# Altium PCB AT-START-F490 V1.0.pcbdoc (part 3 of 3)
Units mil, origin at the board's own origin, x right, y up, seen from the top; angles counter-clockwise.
Board outline 15424.54 x 3536.36 mil, 2 copper layers (Top Layer, Bottom Layer); 130 components, 126 nets, 528 pads, 715 vias.
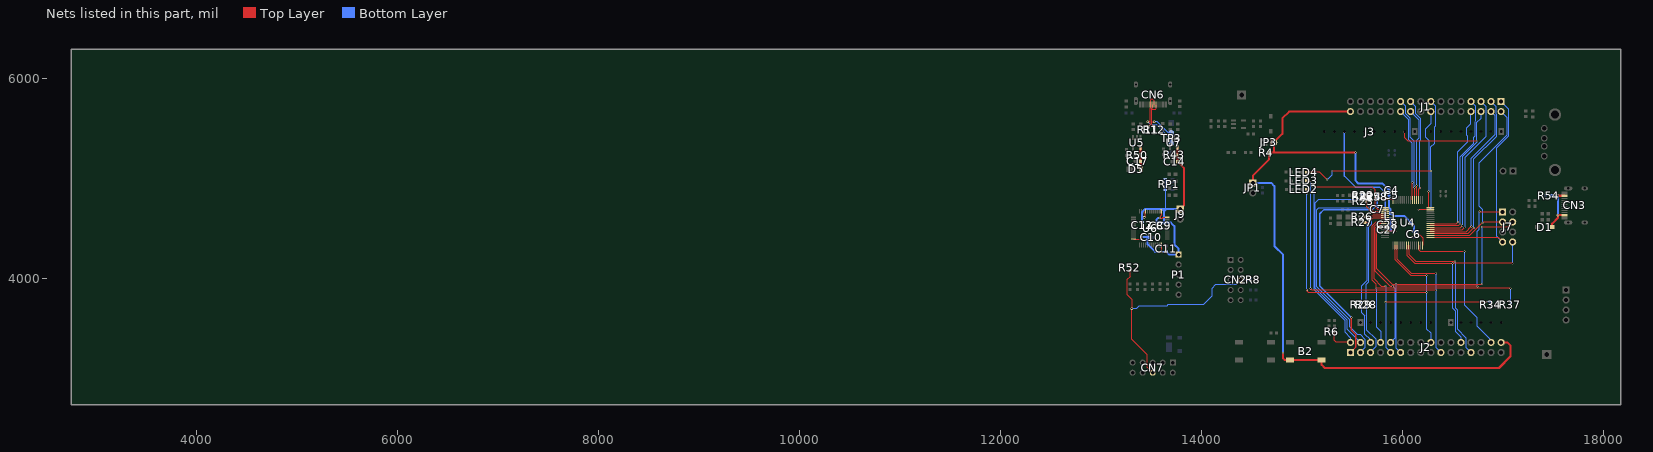
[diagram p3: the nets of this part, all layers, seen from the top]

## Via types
v1: diameter 19.68, hole 11.81, Top Layer to Bottom Layer, 622 vias
v2: diameter 19.69, hole 11.81, Top Layer to Bottom Layer, 42 vias
v3: diameter 23.62, hole 11.81, Top Layer to Bottom Layer, 17 vias
v4: diameter 27.56, hole 13.78, Top Layer to Bottom Layer, 15 vias
v5: diameter 19.7, hole 11.81, Top Layer to Bottom Layer, 10 vias
v6: diameter 24, hole 12, Top Layer to Bottom Layer, 7 vias
v7: diameter 27.56, hole 15.75, Top Layer to Bottom Layer, 2 vias

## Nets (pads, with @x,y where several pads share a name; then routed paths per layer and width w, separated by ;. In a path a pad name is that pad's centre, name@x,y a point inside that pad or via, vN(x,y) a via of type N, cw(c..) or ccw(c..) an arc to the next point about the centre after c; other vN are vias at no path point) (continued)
PB11: J2.30 U4.30 | length 1523.4
  Top Layer w6: U4.30@16161.84,4334.34 16161.84,4289.61 16176.7,4274.76 16617.38,4274.76 v1(16617.58,4274.56)
  Bottom Layer w6: v1(16617.58,4274.56) 16617.58,3743.57 16740.58,3620.57 16740.58,3533.57 J2.30@16883.87,3390.28 ; J2.30@16883.88,3368.14 J2.30@16883.88,3390.26
PB12: J1.1 J7.7 U4.33 | length 2241.6
  Top Layer w6: U4.33@16279.94,4413.07 16952.97,4413.07 J7.7@16998.88,4367.16
  Bottom Layer w6: J1.1@16983.44,5765.86 17056.58,5692.73 17056.58,5420.56 16937.58,5301.56 16937.58,4428.47 J7.7@16998.88,4367.16
PB13: J1.2 J7.3 U4.34 | length 2038.6
  Top Layer w6: U4.34@16279.94,4432.76 16673.28,4432.76 16807.69,4567.16 J7.3@16998.88,4567.16
  Bottom Layer w6: v1(16796.58,4555.56) 16796.58,4692.56 16760.58,4728.56 16760.58,5153.56 17039.58,5432.56 17039.58,5609.73 J1.2@16983.44,5665.86
PB14: J1.3 U4.35 | length 1831.9
  Top Layer w6: U4.35@16279.94,4452.44 16657.45,4452.44 v1(16713.58,4508.56)
  Bottom Layer w6: v1(16713.58,4508.56) 16713.58,5194.56 16940.58,5421.56 16940.58,5634.56 16933.58,5641.56 16933.58,5715.73 J1.3@16883.44,5765.86
PB15: J1.4 U4.36 | length 1689.3
  Top Layer w6: U4.36@16279.94,4472.13 16638.14,4472.13 v1(16688.58,4522.56)
  Bottom Layer w6: v1(16688.58,4522.56) 16688.58,5200.56 16926.58,5438.56 16926.58,5622.73 J1.4@16883.44,5665.86
PC0: J2.8 R37.1 U4.8 | length 2824.2
  Top Layer w6: U4.8@15827.2,4570.55 15826.45,4571.3 15738.83,4571.3 15698.56,4531.03 15698.56,3988.28 15740.1,3946.74 15740.1,3907.72 v1(15739.58,3907.2) 17075.94,3907.2 v1(17076.58,3906.57)
  Bottom Layer w6: v1(15739.58,3907.2) 15739.58,3522.95 15783.88,3478.65 J2.8@15783.88,3368.14 ; R37.1@17076.58,3763.97 v1(17076.58,3906.57)
PC1: J2.9 R34.1 U4.9 | length 2523.7
  Top Layer w6: U4.9@15827.2,4550.87 15743.56,4550.87 15713.42,4520.73 15713.42,4007.78 15792.64,3928.57 v1(15834.58,3928.57) ; v1(15834.61,3768.57) v2(16842.58,3768.57)
  Bottom Layer w6: v1(15834.58,3928.57) v1(15834.61,3768.57) 15834.58,3317.45 J2.9@15883.88,3268.14 ; v2(16842.58,3768.57) R34.1@16880.08,3768.57 ; R34.1@16878.83,3769.82 R34.1@16880.08,3768.57 ; R34.1@16881.83,3766.82 R34.1@16880.08,3768.57
PC2: J2.10 J7.1 U4.10 | length 3185.5
  Top Layer w6: U4.10@15827.2,4531.18 15756.07,4531.18 15727.8,4502.91 15727.8,4080.72 15880.95,3927.57 v1(15903.58,3927.57) 16745.58,3927.57 v1(16746.58,3926.57) ; v1(16766.58,4669.56) 16996.47,4669.56 J7.1@16998.88,4667.16
  Bottom Layer w6: J2.10@15883.88,3368.14 15924.58,3408.84 15924.58,3906.57 v1(15903.58,3927.57) ; v1(16746.58,3926.57) 16746.58,4474.05 16766.58,4494.05 v1(16766.58,4669.56)
PC3: J2.11 J7.4 U4.11 | length 3185.9
  Top Layer w6: U4.11@15827.2,4511.5 15775.09,4511.5 15742.77,4479.18 15742.77,4104.83 15899.81,3947.79 v1(15936.58,3947.79) ; v1@15934.58,3949.79 v1(15936.58,3947.79) ; v1(16795.28,4517.56) 17049.28,4517.56 J7.4@17098.88,4567.16 ; v1(16795.58,3948.57) 16794.58,3947.57 15936.8,3947.57 v1(15936.58,3947.79)
  Bottom Layer w6: v1(15936.58,3947.79) 15936.58,3315.45 J2.11@15983.88,3268.14 ; v1(16795.28,4517.56) 16795.28,3948.86 v1(16795.58,3948.57)
PC4: J2.24 J7.8 U4.24 | length 2222.8
  Top Layer w6: U4.24@16043.73,4334.34 16044.01,4334.07 16044.01,4235.23 16124.67,4154.56 v2(16498.58,4154.56) v1(17099.58,4154.56)
  Bottom Layer w6: v2(16498.58,4154.56) 16498.58,3713.57 16526.58,3685.57 16526.58,3480.03 16583.88,3422.74 J2.24@16583.88,3368.14 ; J7.8@17098.88,4367.16 17099.58,4366.47 v1(17099.58,4154.56)
PC5: J2.25 U4.25 | length 1552.9
  Top Layer w6: U4.25@16063.41,4334.34 16063.41,4243.68 16133.53,4173.56 v2(16525.58,4173.56)
  Bottom Layer w6: v2(16525.58,4173.56) 16525.58,3714.43 16544.58,3695.43 16544.58,3503.7 16632.58,3415.7 16632.58,3319.43 J2.25@16683.88,3268.14
PC6: J1.5 U4.37 | length 1705.6
  Top Layer w6: U4.37@16279.94,4491.81 16596.82,4491.81 v1(16619.58,4514.56)
  Bottom Layer w6: v1(16619.58,4514.56) 16619.58,5207.56 16828.58,5416.56 16828.58,5720.73 J1.5@16783.44,5765.86
PC7: J1.6 J3.2 U4.38 | length 2329.7
  Top Layer w6: J3.2@16023.88,5466.56 16023.88,5407.49 16060.81,5370.56 v2(16742.58,5370.56) ; U4.38@16279.94,4511.5 16576.51,4511.5 v1(16596.42,4531.41)
  Bottom Layer w6: v1(16596.42,4531.41) 16596.42,5215.93 16742.58,5362.08 v2(16742.58,5370.56) 16742.58,5559.56 16783.44,5600.44 J1.6@16783.44,5665.86
PC8: J1.7 U4.39 | length 1606.8
  Top Layer w6: U4.39@16279.94,4531.18 16557.19,4531.18 v1(16575.22,4549.21)
  Bottom Layer w6: v1(16575.22,4549.21) 16575.22,5218.21 16708.87,5351.85 16708.87,5408.23 16726.58,5425.94 16726.58,5566.56 16733.58,5573.56 16733.58,5717.56 16685.28,5765.86 J1.7@16683.44,5765.86
PC9: J1.8 U4.40 | length 1442.8
  Top Layer w6: U4.40@16279.94,4551.69 16538.7,4551.69 v2(16553.58,4566.56)
  Bottom Layer w6: v2(16553.58,4566.56) 16553.58,5265.56 16652.58,5364.56 16652.58,5418.56 16640.58,5430.56 16640.58,5503.56 16683.44,5546.44 J1.8@16683.44,5665.86
PC10: J1.19 U4.51 | length 1030.1
  Top Layer w6: U4.51@16161.84,4787.08 16161.84,4893.64 v2(16174.77,4906.56)
  Bottom Layer w6: J1.19@16083.44,5765.86 16134.58,5714.73 16134.58,5642.56 16184.58,5592.56 16184.58,5386.56 16174.77,5376.76 v2(16174.77,4906.56)
PC11: J1.20 U4.52 | length 925
  Top Layer w6: U4.52@16142.15,4787.08 16142.15,4930.14 v2(16142.58,4930.56)
  Bottom Layer w6: J1.20@16083.44,5665.86 16168.58,5580.73 16168.58,5404.56 16142.58,5378.56 v2(16142.58,4930.56)
PC12: J1.21 U4.53 | length 1036.4
  Top Layer w6: v2(16120.57,4910.16) 16122.47,4908.25 U4.53@16122.47,4787.08
  Bottom Layer w6: J1.21@15983.44,5765.86 16032.58,5716.73 16032.58,5644.56 16078.58,5598.56 16078.58,5412.56 16120.57,5370.57 v2(16120.57,4910.16)
PC13: J2.2 R6.2 U4.2 | length 2859.6
  Top Layer w6: v1(15116.58,4912.56) 15702.58,4912.56 15728.58,4886.56 15728.58,4719.56 15759.48,4688.66 U4.2@15827.2,4688.66 ; R6.2@15317.85,3474.57 15322.76,3474.57 15320.58,3472.38 15320.58,3391.57 15344,3368.14 J2.2@15483.88,3368.14
  Bottom Layer w6: v1(15116.58,4912.56) 15116.58,3896.57 15425.58,3587.57 15425.58,3472.57 15483.88,3414.27 J2.2@15483.88,3368.14
PC14: J2.3 R24.2 | length 2278.3
  Bottom Layer w6: J2.3@15583.88,3268.14 15633.58,3317.84 15633.58,3396.57 15586.58,3443.57 15554.58,3443.57 15475.58,3522.57 15475.58,3593.57 15147.58,3921.57 15147.58,4688.56 15169.58,4710.56 15659.58,4710.56 15689.58,4740.56 R24.2@15689.58,4794.28
PC14/LEXT_IN: R22.1 R24.1 U4.3 | length 429.8
  Top Layer w6: R22.1@15637.08,4832.56 15688.55,4832.56 ; v1(15688.58,4881.56) 15688.58,4832.56 15688.58,4696.56 15716.16,4668.98 U4.3@15827.2,4668.98
  Bottom Layer w6: v1(15688.58,4881.56) 15689.58,4880.56 R24.1@15689.58,4838.69
PC15: J2.4 R25.2 | length 2051.5
  Bottom Layer w6: J2.4@15583.58,3368.57 15450.58,3501.57 15450.58,3590.57 15132.58,3908.57 15132.58,4756.68 15170.18,4794.28 15593.58,4794.28
PC15/LEXT_OUT: R23.1 R25.1 U4.4 | length 399.8
  Top Layer w6: R23.1@15639.08,4774.56 v1(15639.08,4739.92) 15639.08,4722.06 15711.85,4649.29 U4.4@15827.2,4649.29
  Bottom Layer w6: R25.1@15605.58,4838.69 15605.69,4838.56 15633.58,4838.56 15639.08,4833.06 v1(15639.08,4739.92)
PD2: J1.22 U4.54 | length 927.5
  Top Layer w6: v2@16100.16,4959.76 16100.16,4790.7 16102.78,4788.08 U4.54@16102.78,4787.08
  Bottom Layer w6: J1.22@15983.58,5665.56 16064.58,5584.56 16064.58,5387.45 16099.16,5352.87 v2(16099.16,4959.76)
PF0: J2.5 R28.2 | length 511.8
  Bottom Layer w6: R28.2@15643.58,3721.28 15642.58,3720.28 15642.58,3495.57 15733.58,3404.57 15733.58,3323.57 15683.88,3273.86 J2.5@15683.88,3268.14
PF0/HEXT_IN: R26.1 R28.1 U4.5 | length 1085.9
  Top Layer w6: R26.1@15628.08,4616.56 15629.17,4615.47 v1(15671.97,4615.33) 15686.43,4629.78 15778.95,4629.78 15779.08,4629.91 15826.9,4629.91 U4.5@15827.2,4629.61
  Bottom Layer w6: R28.1@15643.58,3765.68 15643.58,3948.57 15665.58,3970.57 15665.58,4518.7 15694.58,4547.7 15694.58,4592.72 v1(15671.97,4615.33)
PF1: J2.6 R29.2 | length 393.2
  Bottom Layer w6: R29.2@15589.58,3722.28 15589.58,3670.57 15628.58,3631.57 15628.58,3447.57 15683.88,3392.26 J2.6@15683.88,3368.14
PF1/HEXT_OUT: R27.1 R29.1 U4.6 | length 1051.4
  Top Layer w6: R27.1@15628.08,4562.56 v1(15670.58,4562.56) 15670.58,4568.08 15711.91,4609.41 15826.7,4609.41 U4.6@15827.2,4609.92
  Bottom Layer w6: R29.1@15589.58,3766.68 15589.58,3925.57 15647.58,3983.57 15647.58,4539.56 v1(15670.58,4562.56)
PF4: J2.18 LED2.2 U4.18 | length 3412.9
  Top Layer w6: v1(15049.23,3891.48) 15049.23,3881.04 15064.35,3865.91 v1(16240.58,3865.91) ; v1(15049.23,4849.22) 15049.53,4849.52 LED2.2@15049.53,4890.77 ; U4.18@15925.62,4334.34 15925.62,4195.52 16085.58,4035.57 v2(16240.58,4035.57)
  Bottom Layer w6: v1(15049.23,3891.48) v1(15049.23,4849.22) ; v2(16240.58,4035.57) v1(16240.58,3865.91) 16240.58,3506.57 16283.88,3463.28 J2.18@16283.88,3368.14
PF5: J2.19 LED3.2 U4.19 | length 3753.8
  Top Layer w6: LED3.2@15049.53,4976.77 v1(15085.37,4976.77) ; v1(15085.37,3904.35) 15102.48,3887.25 v1(16333.58,3887.25) ; U4.19@15945.3,4334.34 15945.3,4200.84 16090.58,4055.57 v2(16333.58,4055.57)
  Bottom Layer w6: v1(15085.37,3904.35) v1(15085.37,4976.77) ; v2(16333.58,4055.57) v1(16333.58,3887.25) 16333.58,3318.43 J2.19@16383.88,3268.14
PF6: J1.15 LED4.2 U4.47 | length 2675.8
  Top Layer w6: LED4.2@15049.53,5060.77 15179.37,5060.77 v1(15251.58,4988.56) ; v1(15302.58,5074.56) v2(16284.58,5074.56) ; v1@16158.95,4688.66 U4.47@16279.94,4688.66
  Bottom Layer w6: v1(15251.58,4988.56) 15302.58,5039.56 v1(15302.58,5074.56) ; v1(16158.9,4688.61) 16268.53,4688.61 16284.58,4704.66 v2(16284.58,5074.56) 16284.58,5314.56 16322.58,5352.56 16322.58,5512.56 16332.58,5522.56 16332.58,5716.73 J1.15@16283.44,5765.86
PF7: J1.16 U4.48 | length 1008.5
  Top Layer w6: v2(16261.58,4870.56) 16263.12,4869.02 16263.12,4711.82 16266.6,4708.35 U4.48@16279.94,4708.35
  Bottom Layer w6: v2(16261.58,4870.56) 16262.58,4871.56 16262.58,5382.56 16230.58,5414.56 16230.58,5490.56 16283.44,5543.44 J1.16@16283.44,5665.86
SWO: CN2.6 CN7.6 R8.2 R52.1 | length 2484.5
  Top Layer w6: R52.1@13290.15,4081.97 13290.15,4024.01 13256.58,3990.45 13256.58,3846.57 13306.58,3796.57 v3(13306.58,3704.57) 13306.58,3399.57 13462.58,3243.57 13462.58,3119.78 CN7.6@13515.34,3067.01
  Bottom Layer w6: v3(13306.58,3704.57) 13350.58,3704.57 13374.58,3728.57 13653.58,3728.57 13665.58,3740.57 14016.58,3740.57 14101.58,3825.57 14101.58,3904.57 14139.58,3942.57 14343.65,3942.57 CN2.6@14390.92,3989.84 ; CN2.6@14390.97,3989.89 R8.2@14490.58,3989.89
USB+: CN6.A6 CN6.B6 R11.1 TP3.3 | length 723.2
  Top Layer w11.2: v4(13466.68,5563.67) 13490.33,5563.67 ; R11.1@13469.58,5515.56 13490.33,5536.31 13490.33,5563.67 ; CN6.A6@13528.38,5735.27 13528.38,5774.77 13516.58,5786.56 13499.58,5786.56 13489.58,5776.56 13489.58,5735.77 CN6.B6@13489.08,5735.27 13489.08,5699.11 13490.33,5697.86 13490.33,5563.67
  Bottom Layer w11.2: v4(13466.68,5563.67) 13497.78,5532.56 13553.58,5532.56 13699.92,5386.22 TP3.3@13699.92,5351.02
USB-: CN6.A7 CN6.B7 R12.1 TP3.2 | length 554.9
  Top Layer w11.2: CN6.A7@13508.77,5735.27 13508.77,5699.11 13507.52,5697.86 13507.52,5683.94 ; R12.1@13528.58,5515.23 13507.52,5536.27 13507.52,5563.67 ; v4(13531.68,5563.67) 13507.52,5563.67 ; CN6.B7@13548.08,5735.27 13548.08,5693.06 13539.58,5684.56 13508.15,5684.56 13507.52,5683.94 ; 13507.52,5563.67 13507.52,5683.94
  Bottom Layer w11.2: v4(13531.68,5563.67) 13561.47,5563.67 13674.12,5451.02 TP3.2@13699.92,5451.02
VBUS_FS: CN3.A4B9 CN3.B4A9 D1.1 R54.2 | length 531.4
  Top Layer w20: D1.1@17492.58,4515.56 17492.58,4550.28 17549.08,4606.78 v6(17549.08,4635.06) CN3.A4B9@17615.28,4635.06 ; v6(17549.08,4827.06) 17550.08,4828.06 CN3.B4A9@17615.28,4828.06
  Bottom Layer w6: R54.2@17485.58,4827.56 v6@17548.58,4827.56
  Bottom Layer w20: v6@17548.58,4827.56 v6(17549.08,4827.06) v6(17549.08,4635.06)
VCC: C8.1 C9.1 C10.1 C11.1 C12.1 C14.1 J9.1 P1.1 R43.2 RP1.1 RP1.2 RP1.3 RP1.4 U6.1 U6.9 U6.24 U6.36 U6.48 U7.5 | length 3073.1
  Top Layer w10: U6.24@13324.5,4397.43 13390.33,4397.43 v3(13407.92,4415.02) ; v3(13430.58,4612.56) 13442.6,4624.6 U6.9@13442.6,4673.02 ; U6.36@13600.08,4338.36 13600.08,4270.27 v3(13600.34,4270.02) ; U6.1@13600.08,4673.02 13600.08,4632.76 13583.34,4616.02 v3(13583.34,4606.02) 13612.34,4606.02 13620.3,4613.97 U6.48@13659.15,4613.97
  Top Layer w20: C14.1@13764.14,5165.56 13827.58,5102.12 13827.58,4732.16 J9.1@13789.38,4693.97 ; C14.1@13764.34,5166.3 U7.5@13764.34,5307.9
  Bottom Layer w10: 13638.82,4683.98 13640.58,4685.73 13640.58,4694.02 RP1.1@13640.58,4887.56 RP1.2@13640.58,4922.99 RP1.3@13640.58,4958.44 RP1.4@13640.58,4993.86
  Bottom Layer w20: C12.1@13407.34,4560.02 13407.34,4664.02 13437.34,4694.02 13610.53,4694.02 ; 13407.35,4614.02 13429.12,4614.02 v3(13430.58,4612.56) ; v3(13407.92,4415.02) 13465.34,4415.02 13465.34,4345.02 13540.34,4270.02 v3(13600.34,4270.02) 13650.58,4273.06 13681.08,4242.56 P1.1@13772.58,4242.56 13772.58,4300.56 13730.34,4342.8 13730.34,4526.02 13696.34,4560.02 C9.1@13628.34,4560.02 ; v3(13583.34,4606.02) 13567.34,4606.02 13554.34,4593.02 13554.34,4560.02 C9.1@13628.34,4560.02 ; J9.1@13789.34,4694.02 13649.06,4694.02 ; 13610.53,4694.02 13610.53,4691.52 13628.34,4673.7 ; 13610.53,4694.02 13640.58,4694.02 13649.06,4694.02 ; C9.1@13628.34,4560.02 13628.34,4673.7 ; 13628.34,4673.7 13638.82,4683.98 13649.06,4694.02
VCC3.5V: C17.1 D5.2 R50.2 U5.5 | length 488.1
  Top Layer w20: U5.5@13395.58,5305.56 13395.15,5110.74 D5.2@13396.33,5109.56
  Top Layer w25: D5.2@13389.33,5099.56 D5.2@13395.14,5105.38 ; U5.5@13395.15,5305.9 C17.1@13395.14,5173.56 ; D5.2@13397.33,5091.56 13395.14,5093.76 D5.2@13395.14,5105.38 ; D5.2@13395.15,5105.39 13395.15,5110.74 C17.1@13395.14,5173.56 ; D5.2@13395.14,5105.38 C17.1@13395.14,5173.56
VDD: B2.1 B2.2 C4.1 C5.1 C6.1 C7.1 J1.32 J2.1 J2.32 JP1.1 JP3.2 L1.1 R4.1 R58.1 R58.2 U4.1 U4.32 U4.64 | length 10829.2
  Top Layer w8: v1(15795.42,4732.19) 15795.42,4724.91 15796.98,4723.34 15796.98,4716.21 U4.1@15800,4713.19 ; U4.1@15800.26,4713.45 U4.1@15800,4713.19 ; U4.1@15827.2,4708.35 15800,4708.35 U4.1@15800,4713.19 ; v1(15869.11,4792.31) 15900.71,4792.31 U4.64@15905.93,4787.08 ; v1(16156.5,4454.44) 16201.21,4409.72 U4.32@16201.21,4334.34
  Top Layer w15: J2.1@15483.88,3268.14 15534.58,3318.84 15534.58,3446.57 15493.58,3487.57 v1(15493.58,3614.57) ; v1(15799.83,4792.31) v1(15869.11,4792.31)
  Top Layer w20: JP1.1@14511.57,4956.56 14511.57,5028.56 14675.08,5192.06 R4.1@14675.08,5258.56 14720.43,5258.56 14720.58,5258.71 ; v1(14813.58,3262.57) 14813.58,3209.57 14830.58,3192.57 14880.68,3192.57 B2.2@14881.09,3192.99 B2.1@15196.06,3192.99 15196.06,3144.09 15226.58,3113.57 16962.58,3113.57 17076.58,3227.57 17076.58,3338.57 17046.58,3368.57 16984.31,3368.57 J2.32@16983.88,3368.14 ; J1.32@15483.44,5665.86 14873.88,5665.86 14806.58,5598.56 14806.58,5444.56 JP3.2@14720.58,5358.56 14720.58,5258.71 ; v1(15532.72,5258.71) 14720.58,5258.71
  Bottom Layer w15: v1(15493.58,3614.57) 15177.58,3930.57 15177.58,4647.84 15216.3,4686.56 15698.75,4686.56 15734.25,4722.06 C7.1@15750.58,4722.06 ; R58.2@15750.58,4796.28 C7.1@15750.58,4722.06 ; R58.1@15750.58,4840.69 15790.45,4840.69 15799.83,4831.31 v1(15799.83,4792.31) ; v1(15795.42,4732.19) 15760.7,4732.19 C7.1@15750.58,4722.06
  Bottom Layer w20: JP1.1@14511.57,4956.56 14694.58,4956.56 14726.58,4924.56 14726.58,4327.56 14813.58,4240.56 v1(14813.58,3262.57) ; v1(15532.72,5258.71) 15532.72,4980.88 15564.04,4949.56 15804.08,4949.56 C4.1@15869.08,4884.56 v1(15869.11,4792.31) 15869.11,4709.03 15883.58,4694.56 15883.58,4654.88 L1.1@15884.58,4653.88 15910.67,4627.78 16019.22,4627.78 16115.6,4531.4 C6.1@16115.6,4469.83 ; C6.1@16117.53,4467.9 16143.03,4467.9 v1(16156.5,4454.44)
VDDA: C27.2 C28.2 J3.8 L1.2 U4.13 | length 1487.2
  Top Layer w9: U4.13@15829.66,4472.59 v2@15931.98,4472.59
  Bottom Layer w15: J3.8@15423.88,5466.56 15423.88,5023.91 15533.22,4914.56 15773.58,4914.56 15832.58,4855.56 15832.58,4607.56 15846.9,4593.24 L1.2@15884.58,4593.24 C28.2@15884.58,4537.56 ; C27.2@15884.58,4488.56 15898.55,4474.59 v2(15931.98,4474.59)
  Bottom Layer w20: C27.2@15884.58,4488.56 C28.2@15884.58,4537.56
pads on no net: CN3.A8 CN3.B8 CN6.A8 CN6.B8 J2.13 J4.1 J4.8 U6.2 U6.3 U6.4 U6.5 U6.6 U6.14 U6.15 U6.16 U6.17 U6.18 U6.21 U6.22 U6.29 U6.38 U6.41 U6.42 U6.43 U6.45 U6.46

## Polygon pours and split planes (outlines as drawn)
GND on Bottom Layer (solid, remove dead copper, pour order 4): 17151.58,5987.56 17151.58,5631.4 17408.58,5629.56 17455.58,5607.56 17455.58,4872.56 17699.58,4872.56 17699.58,4588.86 17594.58,4586.56 17595.17,4511.56 17700.57,4512.19 17701.58,3042.57 13183.5,3041.64 13182.58,3042.57 13182.58,5728.56 13368.58,5728.56 13368.58,5808.56 13373.58,5813.56 13662.58,5813.56 13662.58,5732.56 13939.58,5732.56 13939.58,5984.56 13942.98,5987.97 17151.17,5987.97
GND on Top Layer (solid, remove dead copper, pour order 0): 17151.58,5681.37 17151.58,5632.56 17151.54,5681.37
GND on Bottom Layer (solid, remove dead copper, pour order 6): 17604.57,4095.86 17604.58,4095.57 17604.58,4096.56
GND on Top Layer (solid, remove dead copper, pour order 2): 17151.58,5987.56 17151.58,5632.56 17408.58,5629.56 17455.58,5607.56 17455.58,4872.56 17699.83,4872.27 17699.58,4592.56 17699.58,4588.56 17595.58,4586.56 17595.58,4511.56 17700.58,4511.56 17700.58,3970.57 17701.58,3042.57 13182.58,3042.57 13182.58,5727.56 13181.58,5728.56 13368.58,5728.56 13368.58,5793.28 13348.48,5813.38 13662.39,5813.38 13662.58,5813.56 13662.58,5732.56 13940.58,5732.56 13940.58,5985.56 13942.58,5987.56

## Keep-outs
Top Layer:
  region: 13642.58,4450.56 13675.58,4450.56 13675.58,4443.56 13642.58,4443.56
Board Outline Layer:
  circle w1: c17792.21,5903.56 r62.99
  circle w10: c17792.21,5903.56 r62.99
  circle w1: c17791.58,3128.57 r62.99
  circle w10: c17791.58,3128.57 r62.99
  circle w1: c14044.58,3128.57 r62.99
  circle w10: c14044.58,3128.57 r62.99
  circle w1: c14044.58,5903.56 r62.99
  circle w10: c14044.58,5903.56 r62.99
  circle w1: c17083.58,4866.56 r62.99
  circle w10: c17083.58,4866.56 r62.99
  circle w1: c15033.58,3566.57 r62.99
  circle w10: c15033.58,3566.57 r62.99
  circle w1: c15083.58,5466.56 r62.99
  circle w10: c15083.58,5466.56 r62.99
  lines w8: 13799.95,3001.67 ccw(c13802.87,3080.36) 13881.61,3080.36 13881.87,3519.01 13921.13,3519.01 13921.13,3080.36 ccw(c13999.87,3080.36) 13999.87,3001.62 ; 13802.87,6030.91 cw(c13802.87,5952.17) 13881.61,5952.17 13881.61,5632.02 13921.13,5632.02 13921.13,5951.91 cw(c13999.87,5951.91) 13999.87,6030.65 ; 13920.13,4826.02 13881.87,4826.02 13881.87,3810.02 ; 13920.87,4825.28 13920.87,3810.01 13881.87,3810.01 ; 13881.87,3810.02 13881.87,3810.01 ; 13881.87,3607.01 13881.87,3699.01 13921.13,3699.01 13921.13,3607.01 13881.87,3607.01 ; 13881.87,4904.02 13881.87,5554.02 13921.13,5554.02 13921.13,4904.27 13920.87,4904.02 13881.87,4904.02
  lines w10: 13999.24,3001.05 ccw(c13999.87,3005.02) 13999.87,3001 ; 13999.87,6031.43 ccw(c13999.9,6035.44) 13999.9,6031.43 ; 17836.3,5974.43 cw(c17836.87,5970.45) 17836.87,5974.47 ; 13149.49,5947.67 cw(c13153.5,5947.67) 13150.15,5949.89 cw(c13232.87,5947.41) 13231.42,6030.16 cw(c13232.87,6026.41) 13232.87,6030.43 ; 13149.49,5947.67 13149.49,5947.67 ; 13149.49,5947.67 13149.9,3082.97 ; 13149.9,3082.97 13149.9,3082.97 ; 13149.9,3082.97 ccw(c13153.92,3082.97) 13150.17,3081.52 ccw(c13232.92,3082.97) 13231.59,3000.23 ccw(c13232.92,3004.02) 13232.92,3000 ; 13232.87,6030.43 13999.81,6030.43 13999.87,6030.43 17281.13,6030.43 17836.3,6030.43 17836.87,6030.47 cw(c17836.87,5947.71) 17919.61,5949.17 cw(c17915.87,5947.71) 17919.89,5947.71 ; 13232.87,6030.43 13232.87,6030.43 ; 13232.92,3000 13232.92,3000 ; 13232.92,3000 13998.61,3000 ; 13998.61,3000 13998.61,3000 ; 13998.61,3000 ccw(c13998.61,3004.02) 13999.24,3000.05 13999.87,3000 17281.13,3000 17836.87,3000 ; 17836.87,3000 17836.87,3000 ; 17836.87,3000 ccw(c17836.87,3082.76) 17919.61,3081.3 ccw(c17915.87,3082.76) 17919.88,3082.76 ; 17919.88,3082.76 17919.88,3082.76 ; 17919.88,3082.76 17919.88,5947.72 ; 17919.88,5947.72 17919.89,5947.71

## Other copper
Top Layer:
  drawing of 538 lines, arcs and shapes, not listed
Bottom Layer:
  drawing of 379 lines, arcs and shapes, not listed

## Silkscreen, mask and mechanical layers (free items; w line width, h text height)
Top Silkscreen Layer:
  circle w50: c17073.58,5765.56 r1
  circle w50: c15389.58,3268.57 r1
  lines w5: 16867.58,5338.56 16869.58,5338.56 ; 17005.58,5355.56 17003.58,5355.56 ; 16869.58,5338.56 16888.58,5357.56 16888.58,5362.56 ; 16869.58,5338.56 16905.58,5338.56 ; 16869.58,5338.56 16871.58,5338.56 16888.58,5355.56 ; 16888.58,5338.56 16885.58,5341.56 16874.58,5341.56 16875.58,5340.56 16880.58,5340.56 16887.08,5347.06 16888.58,5347.06 16897.08,5338.56 16905.58,5338.56 ; 16888.58,5338.56 16888.58,5355.56 ; 16888.58,5338.56 16893.58,5343.56 ; 16888.58,5355.56 16893.58,5350.56 16893.58,5343.56 ; 16888.58,5355.56 16908.58,5335.56 ; 16888.58,5355.56 16888.58,5362.56 ; 16888.58,5362.56 16886.58,5362.56 16859.58,5335.56 16908.58,5335.56 ; 16888.58,5362.56 16915.58,5335.56 16908.58,5335.56 ; 16893.58,5343.56 16900.58,5343.56 16905.58,5338.56 ; 16905.58,5338.56 16908.58,5335.56 ; 16964.58,5358.56 17013.58,5358.56 16986.58,5331.56 16984.58,5331.56 ; 16964.58,5358.56 16957.58,5358.56 16984.58,5331.56 ; 16964.58,5358.56 16967.58,5355.56 ; 16964.58,5358.56 16984.58,5338.56 ; 16967.58,5355.56 16976.08,5355.56 16984.58,5347.06 16986.08,5347.06 16992.58,5353.56 16997.58,5353.56 16998.58,5352.56 16987.58,5352.56 16984.58,5355.56 ; 16967.58,5355.56 16972.58,5350.56 16979.58,5350.56 ; 16967.58,5355.56 17003.58,5355.56 ; 16979.58,5350.56 16984.58,5355.56 ; 16979.58,5350.56 16979.58,5343.56 16984.58,5338.56 ; 16984.58,5331.56 16984.58,5338.56 ; 16984.58,5331.56 16984.58,5336.56 17003.58,5355.56 ; 16984.58,5338.56 16984.58,5355.56 ; 16984.58,5338.56 17001.58,5355.56 17003.58,5355.56
  lines w6: 13364.57,3293.28 13364.57,3592.28 ; 13464.57,3294.28 13464.57,3593.28 ; 13564.57,3294.28 13564.57,3594.28 ; 13666.57,3293.28 13666.57,3587.28
  lines w8: 13462.92,3219.01 13462.92,3259.01 13562.92,3259.01 13562.92,3218.01 ; 13753.47,3273.01 13716.47,3236.01 13677.47,3275.01 13753.47,3275.01 ; 14177.57,4227.19 14177.57,4151.19 14216.57,4190.19 14179.57,4227.19 ; 14240.57,3940.2 14200.57,3940.2 14200.57,4040.2 14241.57,4040.2
  lines w10: 15596.17,5193.72 17011.87,5193.72 ; 15870.08,3854.57 16323.08,3854.57 ; 16458.58,3854.57 17018.58,3854.57
  text "43" at 16451.6,5937.63 h58.98
  text "33" at 16957.6,5937.63 h58.98
  text "53" at 15957.6,5935.63 h58.98
  text "63" at 15451.6,5933.63 h58.98
  text "F6" at 16287.08,5831.97 h53.08 r45
  text "A12*" at 16378.99,5831.79 h53.08 r45
  text "C12" at 15984.96,5831.03 h53.08 r45
  text "A10" at 16476.96,5831.03 h53.08 r45
  text "A8" at 16584.19,5830.26 h53.08 r45
  text "C8" at 16682.19,5830.26 h53.08 r45
  text "B14" at 16882.96,5829.03 h53.08 r45
  text "B7" at 15694.18,5828.26 h53.08 r45
  text "B5" at 15789.86,5827.94 h53.08 r45
  text "B3" at 15886.12,5827.96 h53.08 r45
  text "C10" at 16078.96,5827.03 h53.08 r45
  text "A14" at 16172.96,5827.03 h53.08 r45
  text "B12" at 16988.96,5827.03 h53.08 r45
  text "B8" at 15588.18,5826.26 h53.08 r45
  text "C6" at 16788.19,5826.26 h53.08 r45
  text "GND" at 15477.48,5820.27 h53.08 r45
  text "GND" at 14501.58,5796.56 h70.78
  text "B9" at 15582.18,5532.26 h53.08 r45
  text "F11" at 15670.58,5531.56 h44.24 r45
  text "F7" at 16281.08,5527.97 h53.08 r45
  text "D2" at 15986.81,5526.81 h53.08 r45
  text "C11" at 16080.28,5527.02 h53.08 r45
  text "C9" at 16684.19,5526.26 h53.08 r45
  text "B6" at 15783.88,5523.94 h53.08 r45
  text "B4" at 15880.15,5523.96 h53.08 r45
  text "A9" at 16584.19,5524.26 h53.08 r45
  text "C7" at 16784.19,5524.26 h53.08 r45
  text "A15" at 16178.96,5519.03 h53.08 r45
  text "B15" at 16874.96,5519.03 h53.08 r45
  text "B13" at 16986.96,5519.03 h53.08 r45
  text "A11*" at 16475.74,5517.81 h53.08 r45
  text "A13" at 16372.96,5517.03 h53.08 r45
  text "VDD" at 15456.96,5509.03 h53.08 r45
  text "4" at 16617.11,5362.56 h69.7 r90
  text "7" at 16329.11,5360.56 h69.7 r90
  text "2" at 16819.11,5360.56 h69.7 r90
  text "8" at 16163.11,5359.56 h69.7 r90
  text "13" at 15669.7,5335.49 h70.78 r90
  text "12" at 15763.7,5335.49 h70.78 r90
  text "#3" at 16725.7,5317.79 h70.78 r90
  text "#9" at 16063.7,5315.79 h70.78 r90
  text "#6" at 16421.7,5315.79 h70.78 r90
  text "#5" at 16525.7,5315.79 h70.78 r90
  text "IDD" at 14797.34,5312.68 h70.78
  text "#11" at 15867.7,5309.46 h70.78 r90
  text "#10" at 15963.7,5289.76 h70.78 r90
  text "HOST" at 17322.58,5280.56 h70.78 r90
  text "SCL" at 15261.7,5274.56 h70.78 r90
  text "GND" at 15563.7,5270.16 h70.78 r90
  text "SDA" at 15365.7,5267.96 h70.78 r90
  text "TX 1" at 16922.58,5240.56 h70.78 r90
  text "RX 0" at 17024.58,5237.56 h70.78 r90
  text "VDDA" at 15461.7,5220.12 h70.78 r90
  text "DIGITAL(#=PWM)" at 16015.03,5209.08 h61.93
  text "LD:" at 13789.58,5153.56 h61.93 r270
  text "1" at 13790.59,5055.27 h60.99 r270
  text "FS_VBUS" at 16616.58,5039.56 h70.78
  text "AT-Link-EZ V1.4" at 13178.17,5037.22 h88.47 r270
  text "2" at 13790.59,4988.27 h60.99 r270
  text "VDD" at 14304.58,4929.56 h70.8
  text "3" at 13790.59,4915.27 h60.99 r270
  text "4" at 13790.59,4840.27 h60.99 r270
  text "BOOT0" at 14212.58,4817.56 h70.78
  text "5V" at 17174.58,4636.56 h61.93
  text "MISO" at 16788.21,4635.08 h61.93
  text "Device" at 17557.58,4622.56 h70.78 r90
  text "SCK" at 16806.93,4530.08 h61.93
  text "MOSI" at 17174.21,4530.08 h61.93
  text "GND" at 17172.93,4435.08 h61.93
  text "RESET" at 16739.5,4430.08 h61.93
  text "NSS" at 16806.93,4330.08 h61.93
  text "PC4" at 17173.21,4325.08 h61.93
  text "AT-Link" at 14195.75,4276 h88.47
  text "5V" at 14479.65,4160.08 h61.93
  text "3V3" at 14044.93,4154.08 h61.93
  text "SWD" at 14048.93,4060.08 h61.93
  text "BOOT0" at 14483.5,4055.08 h61.93
  text "SWO" at 14480.93,3955.08 h61.93
  text "SWC" at 14045.93,3945.08 h61.93
  text "AT-START-F490 V1.0" at 16086.58,3887.57 h107.4
  text "3V3" at 17441.26,3855.08 h61.93
  text "USART1_RX" at 14488.62,3850.08 h61.93
  text "NRST" at 14052.21,3845.08 h61.93
  text "POWER" at 16111.5,3777.08 h61.93
  text "ANALOG IN" at 16620.62,3777.08 h61.93
  text "USART1_TX" at 17215.26,3759.08 h61.93
  text "GND" at 14050.93,3755.08 h61.93
  text "USART1_TX" at 14488.62,3750.08 h61.93
  text "USART1_RX" at 17214.26,3654.08 h61.93
  text "IOREF" at 15721.7,3646.19 h70.78 r90
  text "RESET" at 15818.7,3645.19 h70.78 r90
  text "AN0" at 16523,3645.41 h70.78 r90
  text "AN1" at 16619,3645.41 h70.78 r90
  text "AN2" at 16724,3644.41 h70.78 r90
  text "AN3" at 16825,3644.41 h70.78 r90
  text "AN4" at 16927,3644.41 h70.78 r90
  text "AN5" at 17027,3644.41 h70.78 r90
  text "3.3V" at 15919.7,3642.72 h70.78 r90
  text "GND" at 16120.7,3641.26 h70.78 r90
  text "GND" at 16219.99,3641.26 h70.78 r90
  text "5V" at 16019.7,3639.79 h70.78 r90
  text "SWD" at 13581.1,3588.5 h61.93 r270
  text "GND" at 13277.09,3584.21 h61.93 r270
  text "SWC" at 13482.09,3584.21 h61.93 r270
  text "3V3" at 13677.09,3584.21 h61.93 r270
  text "NRST" at 13377.09,3582.93 h61.93 r270
  text "GND" at 17443.26,3557.08 h61.93
  text "F4" at 16283.08,3431.97 h53.08 r45
  text "F1*" at 15694.96,3431.03 h53.08 r45
  text "B0" at 16665.51,3431.41 h53.08 r45
  text "B2" at 16771.31,3431.39 h53.08 r45
  text "A0" at 16081.5,3430.24 h53.08 r45
  text "A2" at 16175.33,3430.24 h53.08 r45
  text "A4" at 16373.45,3430.24 h53.08 r45
  text "A6" at 16467.28,3430.24 h53.08 r45
  text "C0" at 15785.88,3427.94 h53.08 r45
  text "C2" at 15882.15,3427.96 h53.08 r45
  text "C4" at 16563.51,3427.94 h53.08 r45
  text "B11" at 16872.57,3426.36 h53.08 r45
  text "C13" at 15473.5,3420.26 h53.08 r45
  text "SWO" at 13483.08,3418.92 h61.93 r270
  text "BOOT0" at 13588.97,3417.87 h46.44 r270
  text "C15*" at 15581.74,3417.81 h53.08 r45
  text "GND" at 15978.58,3415.57 h53.08 r45
  text "VDD" at 16982.58,3415.57 h53.08 r45
  text "RX" at 13276.08,3397.2 h61.93 r270
  text "TX" at 13377.09,3395.9 h61.93 r270
  text "5V" at 13676.08,3395.9 h61.93 r270
  text "GND" at 17529.58,3208.57 h70.78
  text "C1" at 15890.18,3136.26 h53.08 r45
  text "A1" at 16185.5,3134.75 h53.08 r45
  text "NC" at 16086.18,3130.26 h53.08 r45
  text "F5" at 16378.18,3130.26 h53.08 r45
  text "B1" at 16786.19,3130.26 h53.08 r45
  text "C3" at 15984.18,3128.26 h53.08 r45
  text "C5" at 16676.19,3126.26 h53.08 r45
  text "A3" at 16270.09,3125.48 h53.08 r45
  text "A7" at 16578.19,3124.26 h53.08 r45
  text "F0*" at 15674.96,3123.03 h53.08 r45
  text "A5" at 16472.19,3120.26 h53.08 r45
  text "B10" at 16868.96,3113.03 h53.08 r45
  text "C14*" at 15567.74,3109.81 h53.08 r45
  text "VDD" at 15452.58,3106.57 h53.08 r45
  text "GND" at 16964.96,3107.03 h53.08 r45
  text "NRST" at 15745.74,3083.81 h53.08 r45
  text "RESET" at 14441.5,3062.59 h70.78
  text "USER" at 14962.03,3061.59 h70.78
  text "21" at 16464.6,3040.63 h58.98
  text "31" at 16963.6,3039.63 h58.98
  text "11" at 15970.6,3038.63 h58.98
  text "1" at 15475.58,3036.12 h58.08
Bottom Silkscreen Layer:
  text "61" at 15567.12,5811.56 h58.98 r315
  text "59" at 15676.12,5811.56 h58.98 r315
  text "57" at 15777.12,5811.56 h58.98 r315
  text "55" at 15875.12,5811.56 h58.98 r315
  text "53" at 15976.12,5811.56 h58.98 r315
  text "51" at 16076.12,5811.56 h58.98 r315
  text "39" at 16677.12,5811.56 h58.98 r315
  text "37" at 16778.12,5811.56 h58.98 r315
  text "35" at 16877.12,5811.56 h58.98 r315
  text "33" at 16982.12,5811.56 h58.98 r315
  text "63" at 15468.12,5806.56 h58.98 r315
  text "49" at 16179.12,5806.56 h58.98 r315
  text "43" at 16479.12,5806.56 h58.98 r315
  text "47" at 16276.12,5804.56 h58.98 r315
  text "45" at 16374.12,5804.56 h58.98 r315
  text "41" at 16577.12,5804.56 h58.98 r315
  text "64" at 15480.12,5536.56 h58.98 r315
  text "62" at 15580.12,5536.56 h58.98 r315
  text "60" at 15680.12,5536.56 h58.98 r315
  text "58" at 15785.12,5536.56 h58.98 r315
  text "50" at 16187.12,5536.56 h58.98 r315
  text "34" at 16986.12,5536.56 h58.98 r315
  text "52" at 16087.12,5535.56 h58.98 r315
  text "44" at 16489.12,5535.56 h58.98 r315
  text "42" at 16586.12,5535.56 h58.98 r315
  text "38" at 16787.12,5535.56 h58.98 r315
  text "36" at 16889.12,5535.56 h58.98 r315
  text "48" at 16292.12,5534.56 h58.98 r315
  text "46" at 16390.12,5534.56 h58.98 r315
  text "40" at 16688.12,5534.56 h58.98 r315
  text "56" at 15887.12,5531.56 h58.98 r315
  text "54" at 15987.12,5531.56 h58.98 r315
  text "VDD" at 13679.58,4640.56 h53.08 r270
  text "AT32F490RCT7" at 16784.58,4011.57 h176.95
  text "GND" at 13666.58,3790.57 h53.08 r270
  text "2" at 15475.19,3426.83 h58.08 r315
  text "8" at 15773.19,3425.18 h58.08 r315
  text "4" at 15573.19,3423.18 h58.08 r315
  text "6" at 15669.19,3423.18 h58.08 r315
  text "10" at 15878.12,3415.56 h58.98 r315
  text "12" at 15980.12,3415.56 h58.98 r315
  text "16" at 16178.12,3415.56 h58.98 r315
  text "14" at 16076.12,3413.56 h58.98 r315
  text "18" at 16273.12,3413.56 h58.98 r315
  text "20" at 16375.12,3412.56 h58.98 r315
  text "22" at 16482.12,3412.56 h58.98 r315
  text "24" at 16583.12,3412.56 h58.98 r315
  text "26" at 16680.12,3411.56 h58.98 r315
  text "28" at 16788.12,3411.56 h58.98 r315
  text "32" at 16982.12,3408.56 h58.98 r315
  text "30" at 16885.12,3407.56 h58.98 r315
  text "1" at 15465.19,3158.83 h58.08 r315
  text "5" at 15663.19,3157.18 h58.08 r315
  text "9" at 15865.19,3157.18 h58.08 r315
  text "11" at 15966.12,3155.56 h58.98 r315
  text "3" at 15554.46,3155.36 h58.08 r315
  text "7" at 15761.19,3155.18 h58.08 r315
  text "19" at 16378.12,3152.56 h58.98 r315
  text "15" at 16178.12,3151.56 h58.98 r315
  text "13" at 16077.12,3150.56 h58.98 r315
  text "21" at 16480.12,3150.56 h58.98 r315
  text "17" at 16280.12,3147.56 h58.98 r315
  text "31" at 16982.12,3148.45 h58.98 r315
  text "29" at 16895.12,3143.56 h58.98 r315
  text "25" at 16692.12,3140.56 h58.98 r315
  text "23" at 16591.12,3139.56 h58.98 r315
  text "27" at 16788.12,3137.56 h58.98 r315
Mechanical Layer:
  circle w1: c17792.21,5903.56 r62.99
  circle w1: c17791.58,3128.57 r62.99
  circle w1: c14044.58,3128.57 r62.99
  circle w1: c14044.58,5903.56 r62.99
  circle w1: c17083.58,4866.56 r62.99
  circle w1: c15033.58,3566.57 r62.99
  circle w1: c15083.58,5466.56 r62.99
